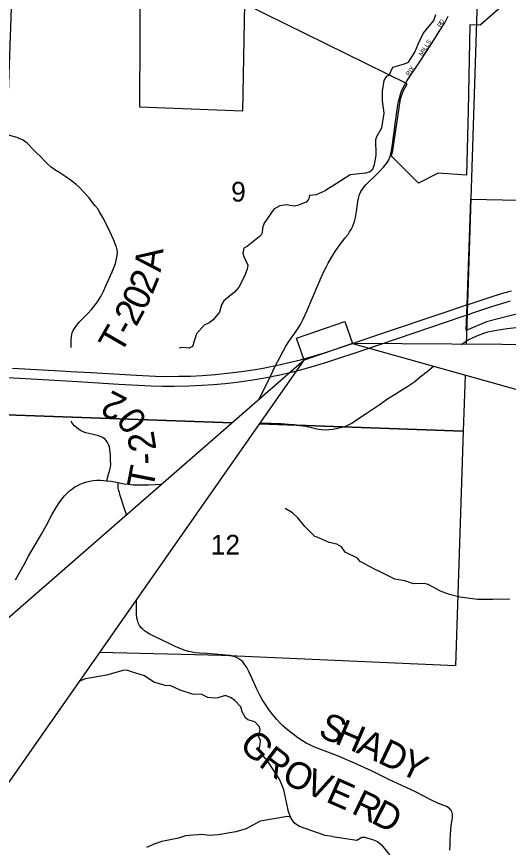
# Model space of a CAD drawing. Extents: x 0 to 34, y 0 to 22.
# Drawn here: x 26.645 to 27.691, y 15.353 to 17.117 of the extents above; entities that cross this region are included whole.
import ezdxf

# ---------------------------------------------------------------- set-up
doc = ezdxf.new("R2010")
doc.units = 0
for name, color, linetype in [('Default', 7, 'Continuous'), ('GM_X_City_Street', 7, 'Continuous'), ('GM_X_City_Street_Text', 7, 'Continuous'), ('GM_X_Corporation', 7, 'Continuous'), ('GM_X_County_Road', 7, 'Continuous'), ('GM_X_Interstate_Route', 7, 'Continuous'), ('GM_X_Minor_River', 7, 'Continuous'), ('GM_X_Section', 7, 'Continuous'), ('GM_X_Section_Text', 7, 'Continuous'), ('GM_X_Township_Road', 7, 'Continuous'), ('GM_X_Township_Road_Text', 7, 'Continuous'), ('SH_Text', 7, 'Continuous')]:
    doc.layers.add(name, color=color, linetype=linetype)

msp = doc.modelspace()

# ---------------------------------------------------------------- linework, layer by layer
at = {"layer": 'Default'}
msp.add_lwpolyline([(27.2402, 16.4341), (27.3429, 16.4694), (27.359, 16.4225), (27.2563, 16.3872)], close=True, dxfattribs=at)
at = {"layer": 'GM_X_City_Street'}
msp.add_lwpolyline([(27.4729, 16.9766), (27.4757, 16.9812), (27.5033, 17.0227), (27.527, 17.0593), (27.5439, 17.0855), (27.5556, 17.1039), (27.5602, 17.1121), (27.563, 17.118)], dxfattribs=at)
at = {"layer": 'GM_X_Corporation'}
for points in [[(27.6751, 17.1377), (27.6304, 17.0991), (27.6088, 17.0999), (27.6051, 16.9178), (27.6016, 16.7802), (27.5417, 16.7845), (27.4998, 16.7633), (27.4425, 16.8209), (27.4451, 16.8328), (27.4614, 16.9424), (27.4669, 16.9589), (27.4753, 16.9746), (27.1299, 17.1443), (27.1252, 16.9163), (26.907, 16.9246), (26.9087, 17.2311)], [(27.6751, 17.1377), (27.6304, 17.0991), (27.6088, 17.0999), (27.6051, 16.9178), (27.6016, 16.7802), (27.5417, 16.7845), (27.4998, 16.7633), (27.4425, 16.8209), (27.4451, 16.8328), (27.4614, 16.9424), (27.4669, 16.9589), (27.4753, 16.9746), (27.1299, 17.1443), (27.1252, 16.9163), (26.907, 16.9246), (26.9087, 17.2311)], [(27.743, 16.4946), (27.644, 16.4686), (27.6009, 16.4506), (27.6029, 16.5052), (27.6108, 16.7296), (27.8455, 16.7243)], [(27.743, 16.4946), (27.644, 16.4686), (27.6009, 16.4506), (27.6029, 16.5052), (27.6108, 16.7296), (27.8455, 16.7243)]]:
    msp.add_lwpolyline(points, dxfattribs=at)
at = {"layer": 'GM_X_County_Road'}
for points in [[(27.1601, 16.3035), (27.1618, 16.3067), (27.1741, 16.3317), (27.1843, 16.3522), (27.196, 16.3757), (27.2046, 16.3927), (27.2117, 16.4064), (27.2178, 16.417), (27.2238, 16.4267), (27.2291, 16.4343), (27.2354, 16.4427), (27.2441, 16.4554), (27.2489, 16.4633), (27.2544, 16.4743), (27.2622, 16.4912), (27.2866, 16.5483), (27.2927, 16.5626), (27.299, 16.5768), (27.3038, 16.5861), (27.3076, 16.5934), (27.3154, 16.6068), (27.3224, 16.6182), (27.3289, 16.6277), (27.3344, 16.6352), (27.3441, 16.6474), (27.3498, 16.6546), (27.3533, 16.6597), (27.3565, 16.6649), (27.3592, 16.6703), (27.3616, 16.6759), (27.3634, 16.6817), (27.3655, 16.6907), (27.3675, 16.7029), (27.3706, 16.7244), (27.3718, 16.7305), (27.3735, 16.7366), (27.3745, 16.7395), (27.3771, 16.7453), (27.3803, 16.7506), (27.384, 16.7557), (27.3881, 16.7604), (27.3947, 16.767), (27.4082, 16.7797), (27.4148, 16.7862), (27.4254, 16.7974), (27.4294, 16.8021), (27.433, 16.807), (27.4347, 16.8096), (27.4363, 16.8126), (27.4374, 16.8147), (27.4383, 16.8167), (27.4404, 16.8228), (27.4422, 16.8321), (27.4451, 16.8507), (27.4468, 16.863), (27.4484, 16.8753), (27.4496, 16.8845), (27.4552, 16.9248), (27.4574, 16.937), (27.4596, 16.9461), (27.4624, 16.955), (27.4659, 16.9636), (27.4729, 16.9765), (27.4729, 16.9766)], [(26.643, 15.9206), (26.6613, 15.9533), (26.671, 15.9709), (26.6807, 15.9879), (26.698, 16.018), (26.7086, 16.0369), (26.7206, 16.0586), (26.7296, 16.0744), (26.7358, 16.0844), (26.7412, 16.092), (26.7469, 16.0992), (26.7528, 16.1049), (26.7576, 16.1095), (26.7619, 16.113), (26.7694, 16.1181), (26.7756, 16.1215), (26.7808, 16.124), (26.7879, 16.1269), (26.7945, 16.1291), (26.8005, 16.1306), (26.8078, 16.1319), (26.8159, 16.1324), (26.8227, 16.1324), (26.83, 16.1321), (26.8362, 16.1313), (26.8378, 16.1312)], [(26.8378, 16.1312), (26.8464, 16.1302), (26.8611, 16.1272)], [(26.8611, 16.1272), (26.8638, 16.1266), (26.874, 16.125), (26.8828, 16.1237), (26.893, 16.1228), (26.9094, 16.1223), (26.9263, 16.1225), (26.9399, 16.1232), (26.9514, 16.1241), (26.9546, 16.1245)]]:
    msp.add_lwpolyline(points, dxfattribs=at)
at = {"layer": 'GM_X_Interstate_Route'}
for points in [[(26.6365, 16.3707), (26.7389, 16.3647), (26.7606, 16.3634), (26.804, 16.361), (26.9002, 16.3555), (26.9406, 16.3537), (26.9655, 16.353), (26.9903, 16.3531), (27.0152, 16.3537), (27.04, 16.355), (27.068, 16.3571), (27.0927, 16.3595), (27.1236, 16.3632), (27.1482, 16.3667), (27.1697, 16.3704), (27.196, 16.3757), (27.1971, 16.3759), (27.2214, 16.3814), (27.2485, 16.3883), (27.2755, 16.3958), (27.3022, 16.404), (27.3554, 16.4215), (27.423, 16.4445), (27.5541, 16.4889), (27.5938, 16.5022), (27.6019, 16.5049), (27.6029, 16.5052), (27.6495, 16.5208), (27.6762, 16.5291), (27.6971, 16.5349)], [(27.606, 16.4845), (27.6154, 16.4877), (27.6322, 16.4934), (27.6557, 16.5012), (27.6953, 16.5131)], [(26.5307, 16.3558), (26.6517, 16.3488), (26.7633, 16.3425), (26.8626, 16.3367), (26.9308, 16.3331), (26.9556, 16.3322), (26.9804, 16.3321), (27.0115, 16.3328), (27.0394, 16.334), (27.0642, 16.3356), (27.0889, 16.3379), (27.1135, 16.3409), (27.1473, 16.3457), (27.1688, 16.3492), (27.1843, 16.3522), (27.1901, 16.3533), (27.2023, 16.3558), (27.2325, 16.3629), (27.2595, 16.3699), (27.2834, 16.3766), (27.3072, 16.3839), (27.3838, 16.4094), (27.5945, 16.4806), (27.606, 16.4845)]]:
    msp.add_lwpolyline(points, dxfattribs=at)
at = {"layer": 'GM_X_Minor_River'}
for points in [[(27.315, 16.7559), (27.3543, 16.7815), (27.3876, 16.7851), (27.3952, 16.7871), (27.4027, 16.7928), (27.4064, 16.8031), (27.4097, 16.8229), (27.409, 16.8563), (27.4109, 16.8624), (27.4217, 16.881), (27.4264, 16.9122), (27.4232, 16.9384), (27.423, 16.9589), (27.4263, 16.9817), (27.4326, 16.9905), (27.4375, 16.9928), (27.445, 17.0095), (27.47, 17.0165), (27.4783, 17.0204), (27.4921, 17.0414), (27.4988, 17.0589), (27.5022, 17.0661), (27.5096, 17.081), (27.5325, 17.1088), (27.5362, 17.1214)], [(27.315, 16.7559), (27.301, 16.7471), (27.2822, 16.7382), (27.2678, 16.7374), (27.2659, 16.7283), (27.2607, 16.7233), (27.2422, 16.7156), (27.2353, 16.7144), (27.219, 16.717), (27.2047, 16.715), (27.1922, 16.7081), (27.1716, 16.6784), (27.1682, 16.6681), (27.1675, 16.6578), (27.1642, 16.6525), (27.1359, 16.6296), (27.1287, 16.6254), (27.1265, 16.6147), (27.1281, 16.6075), (27.1366, 16.5894), (27.1351, 16.5803), (27.1299, 16.5658), (27.1176, 16.5426), (27.1085, 16.5315), (27.0859, 16.5136), (27.0807, 16.5048), (27.0766, 16.4896), (27.0631, 16.4732), (27.0544, 16.4664), (27.0438, 16.4617), (27.0281, 16.443), (27.0195, 16.4161), (27.012, 16.4126), (26.9983, 16.414), (26.9908, 16.4132)], [(27.6935, 15.88), (27.6578, 15.879), (27.6249, 15.8788), (27.5873, 15.8842), (27.5653, 15.8894), (27.5463, 15.8968), (27.5204, 15.9111), (27.5117, 15.9129), (27.4893, 15.912), (27.4707, 15.9187), (27.4491, 15.9223), (27.4156, 15.9392), (27.4073, 15.9429), (27.3753, 15.9594), (27.3699, 15.9666), (27.3437, 15.9793), (27.3357, 15.9906), (27.3261, 15.9962), (27.3098, 16.0003), (27.2844, 16.0111), (27.279, 16.013), (27.258, 16.0341), (27.2431, 16.0526), (27.2317, 16.0628), (27.2164, 16.0721)], [(27.317, 15.3756), (27.3014, 15.3781), (27.2467, 15.3968), (27.2369, 15.4035), (27.2288, 15.4137), (27.2231, 15.4281), (27.2219, 15.4349), (27.2133, 15.4747), (27.2052, 15.4963), (27.1788, 15.5363), (27.1601, 15.5574), (27.1634, 15.5707), (27.1637, 15.5795), (27.1606, 15.5874), (27.1632, 15.6022), (27.1616, 15.6087), (27.1517, 15.6192), (27.1369, 15.6233), (27.1316, 15.6274), (27.1281, 15.6342), (27.1251, 15.6407), (27.122, 15.6513), (27.1094, 15.6648), (27.1014, 15.6701), (27.0892, 15.6753), (27.073, 15.6699), (27.0662, 15.6691), (27.0518, 15.6706), (27.0388, 15.6773), (27.0191, 15.6776), (26.9933, 15.6865), (26.9732, 15.6955), (26.9614, 15.6965), (26.9368, 15.7036), (26.917, 15.7171), (26.8991, 15.7227), (26.8893, 15.7257), (26.8817, 15.7283), (26.8737, 15.729), (26.8363, 15.7185), (26.7917, 15.7103), (26.7788, 15.7053)], [(27.2276, 15.4167), (27.2212, 15.4179), (27.1633, 15.4084), (27.1332, 15.3919), (27.1112, 15.3857), (27.0738, 15.379), (27.0556, 15.3781), (27.0389, 15.3799), (27.0041, 15.3767), (26.9897, 15.372), (26.9538, 15.365), (26.9391, 15.3603), (26.9217, 15.3522)], [(27.317, 15.3756), (27.3685, 15.3679), (27.3794, 15.3744), (27.3851, 15.3745), (27.4022, 15.3696), (27.4128, 15.3648), (27.4212, 15.3576), (27.4377, 15.3365)]]:
    msp.add_lwpolyline(points, dxfattribs=at)
at = {"layer": 'GM_X_Section'}
for points in [[(27.1036, 16.2543), (26.6035, 16.2723), (26.6394, 17.2767), (27.6271, 17.2407), (27.6008, 16.4208)], [(27.5987, 16.3555), (27.5949, 16.2366), (27.1617, 16.2522)], [(26.5857, 15.8032), (26.6035, 16.2723), (27.1036, 16.2543)], [(27.1617, 16.2522), (27.5949, 16.2366), (27.578, 15.7378), (27.0816, 15.7603), (26.8218, 15.7668)]]:
    msp.add_lwpolyline(points, dxfattribs=at)
at = {"layer": 'GM_X_Township_Road'}
for points in [[(26.7881, 16.744), (26.788, 16.7441), (26.7791, 16.7538), (26.7718, 16.7608), (26.7624, 16.7686), (26.75, 16.7767), (26.737, 16.7854), (26.727, 16.7913), (26.7192, 16.7975), (26.7111, 16.8042), (26.7049, 16.8105), (26.6966, 16.8191), (26.6873, 16.8281), (26.6788, 16.8371), (26.6724, 16.8438), (26.6678, 16.848), (26.6629, 16.8518), (26.6576, 16.855), (26.6521, 16.8578), (26.6464, 16.8601), (26.6435, 16.8611), (26.6332, 16.8638), (26.6273, 16.8657)], [(26.7613, 16.4145), (26.7614, 16.4301), (26.7618, 16.4362), (26.7627, 16.4423), (26.7636, 16.4453), (26.7653, 16.4501), (26.7713, 16.459), (26.7791, 16.4685), (26.7869, 16.4768), (26.7969, 16.4868), (26.8044, 16.4949), (26.8104, 16.5019), (26.8174, 16.5114), (26.8241, 16.5227), (26.8302, 16.5339), (26.8353, 16.5452), (26.8484, 16.5747), (26.8554, 16.5928), (26.8587, 16.6059), (26.8591, 16.609), (26.8597, 16.6155), (26.8592, 16.6217), (26.8578, 16.6271), (26.8552, 16.6347), (26.8514, 16.6438), (26.8436, 16.6605), (26.8357, 16.6767), (26.8287, 16.6904), (26.822, 16.701), (26.8177, 16.7085), (26.8125, 16.7153), (26.8066, 16.7225), (26.7993, 16.732), (26.7881, 16.744)], [(27.5904, 16.4209), (27.5965, 16.425), (27.6064, 16.4311), (27.6159, 16.4358), (27.6269, 16.4402), (27.6383, 16.4445), (27.6471, 16.4473), (27.6654, 16.4512), (27.6881, 16.4546), (27.713, 16.4573)], [(27.1628, 16.2537), (27.1856, 16.2535), (27.2075, 16.2526), (27.223, 16.2515), (27.2353, 16.2505), (27.2476, 16.2489), (27.2598, 16.2469), (27.272, 16.2444), (27.2835, 16.2417), (27.2932, 16.2399), (27.3011, 16.2394), (27.3089, 16.2399), (27.3182, 16.2411), (27.3274, 16.2427), (27.3364, 16.2449), (27.3454, 16.2475), (27.3511, 16.2499), (27.3576, 16.2535), (27.3676, 16.2606), (27.3883, 16.2742), (27.4159, 16.2928), (27.4339, 16.305), (27.4497, 16.3149), (27.4602, 16.3216), (27.4771, 16.3318), (27.4917, 16.3423), (27.5033, 16.3517), (27.518, 16.3632), (27.5315, 16.3743)], [(26.8378, 16.1312), (26.838, 16.1322), (26.8389, 16.1371), (26.8398, 16.1415), (26.8409, 16.1456), (26.8427, 16.1512), (26.8438, 16.1543), (26.845, 16.1602), (26.8455, 16.1661), (26.8453, 16.1747), (26.8448, 16.1849), (26.8445, 16.1915), (26.8438, 16.1976), (26.8427, 16.2031), (26.841, 16.2083), (26.8389, 16.2127), (26.836, 16.217), (26.8334, 16.2196), (26.8304, 16.2218), (26.8266, 16.2241), (26.8216, 16.226), (26.8173, 16.2272), (26.8108, 16.2285), (26.7986, 16.2313), (26.7926, 16.2331), (26.7868, 16.2354), (26.7812, 16.2381), (26.7759, 16.2415), (26.7734, 16.2434), (26.7682, 16.248), (26.7641, 16.2528), (26.7611, 16.2575)], [(26.8792, 16.0587), (26.8757, 16.0695), (26.865, 16.1019), (26.8638, 16.1061), (26.8623, 16.1116), (26.8616, 16.1163), (26.8611, 16.121), (26.8611, 16.1254), (26.8611, 16.1272)], [(27.5661, 15.3466), (27.5669, 15.359), (27.5671, 15.3675), (27.5676, 15.3806), (27.5683, 15.3897), (27.5693, 15.3987), (27.5711, 15.4108), (27.5719, 15.4161), (27.5721, 15.4189), (27.572, 15.4217), (27.5716, 15.4244), (27.5707, 15.4272), (27.5696, 15.43), (27.5678, 15.4324), (27.5661, 15.4342), (27.5634, 15.4365), (27.5605, 15.4384), (27.5577, 15.4399), (27.5532, 15.4415), (27.5424, 15.4458), (27.5243, 15.4541), (27.4933, 15.4704), (27.4734, 15.4798), (27.4369, 15.4969), (27.4009, 15.5141), (27.3634, 15.5317), (27.3275, 15.5469), (27.3072, 15.5546), (27.2899, 15.5614), (27.2775, 15.5664), (27.2687, 15.5702), (27.2609, 15.574), (27.2534, 15.5785), (27.2431, 15.5854), (27.2331, 15.5928), (27.2209, 15.6024), (27.2116, 15.6106), (27.2049, 15.6171), (27.1985, 15.6239), (27.1906, 15.6334), (27.183, 15.6432), (27.1741, 15.6559), (27.1674, 15.6664), (27.1629, 15.6746), (27.156, 15.6885), (27.1441, 15.7152), (27.1396, 15.725), (27.134, 15.7361), (27.1308, 15.7406), (27.1262, 15.7467), (27.122, 15.7505), (27.1177, 15.7532), (27.1131, 15.7555), (27.1073, 15.7578), (27.0995, 15.7598), (27.0897, 15.761), (27.0832, 15.7618), (27.0492, 15.7641), (27.0342, 15.7648), (27.0249, 15.7658), (27.0188, 15.7669), (27.0112, 15.7683), (27.0034, 15.7706), (26.9943, 15.7741), (26.9827, 15.7792), (26.9666, 15.7867), (26.9384, 15.8003), (26.9268, 15.8061), (26.9213, 15.8096), (26.9174, 15.8125), (26.915, 15.8144), (26.9127, 15.8165), (26.9105, 15.8187), (26.9086, 15.8211), (26.9069, 15.8237), (26.9054, 15.8264), (26.9041, 15.8292), (26.903, 15.832), (26.9022, 15.8348), (26.9012, 15.8398), (26.9004, 15.8472), (26.9001, 15.8565), (26.9001, 15.875), (26.9001, 15.8786)]]:
    msp.add_lwpolyline(points, dxfattribs=at)
at = {"layer": 'SH_Text'}
for points in [[(27.359, 16.4225), (29.1566, 15.9204), (29.1566, 16.4104)], [(27.2563, 16.3872), (26.3766, 15.621), (26.3766, 15.131)]]:
    msp.add_lwpolyline(points, close=True, dxfattribs=at)

# ---------------------------------------------------------------- texts
at = {"layer": 'GM_X_City_Street_Text'}
for s, rotation, p in [('R', 57.5493, (27.5466, 17.0935)), ('D', 59.0267, (27.5507, 17.1)), ('MILLS', 57.5304, (27.5074, 17.0326)), ('RIX', 56.9757, (27.4799, 16.9901))]:
    msp.add_text(s, height=0.00947, rotation=rotation, dxfattribs=at).set_placement(p)
at = {"layer": 'GM_X_Section_Text'}
for s, height, p in [('9', 0.0419, (27.1014, 16.7242)), ('12', 0.04186, (27.0581, 15.9745))]:
    msp.add_text(s, height=height, rotation=0, dxfattribs=at).set_placement(p)
at = {"layer": 'GM_X_Township_Road_Text'}
for s, rotation, p in [('A', 82.8204, (26.9515, 16.5732)), ('2', 67.4703, (26.9339, 16.5249)), ('0', 64.9332, (26.918, 16.4907)), ('2', 61.4575, (26.8995, 16.4566)), ('T', 60.0638, (26.866, 16.3981)), ('-', 60.3532, (26.8874, 16.4352)), ('2', 152.792, (26.8835, 16.3055)), ('0', 126.5259, (26.9258, 16.2591)), ('2', 99.261, (26.9428, 16.1977)), ('-', 91.9191, (26.9443, 16.1665)), ('T', 78.9523, (26.9351, 16.1108)), ('S', 337.2625, (27.2842, 15.589)), ('H', 336.7636, (27.3194, 15.5742)), ('G', 314.3638, (27.116, 15.5686)), ('A', 335.3218, (27.365, 15.5546)), ('D', 334.4776, (27.4103, 15.5338)), ('R', 322.7105, (27.1578, 15.5269)), ('Y', 334.4418, (27.4554, 15.5123)), ('O', 334.8329, (27.2061, 15.4918)), ('V', 337.8682, (27.2544, 15.4693)), ('E', 336.1728, (27.3003, 15.4506)), ('R', 334.395, (27.3546, 15.4262)), ('D', 332.9201, (27.3963, 15.4062))]:
    msp.add_text(s, height=0.0568, rotation=rotation, dxfattribs=at).set_placement(p)

doc.saveas('drawing.dxf')
